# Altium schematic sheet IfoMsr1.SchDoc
size C; Engineer: Daniel Sigg; DocumentNumber: 4; SheetNumber: 4; SheetTotal: 33
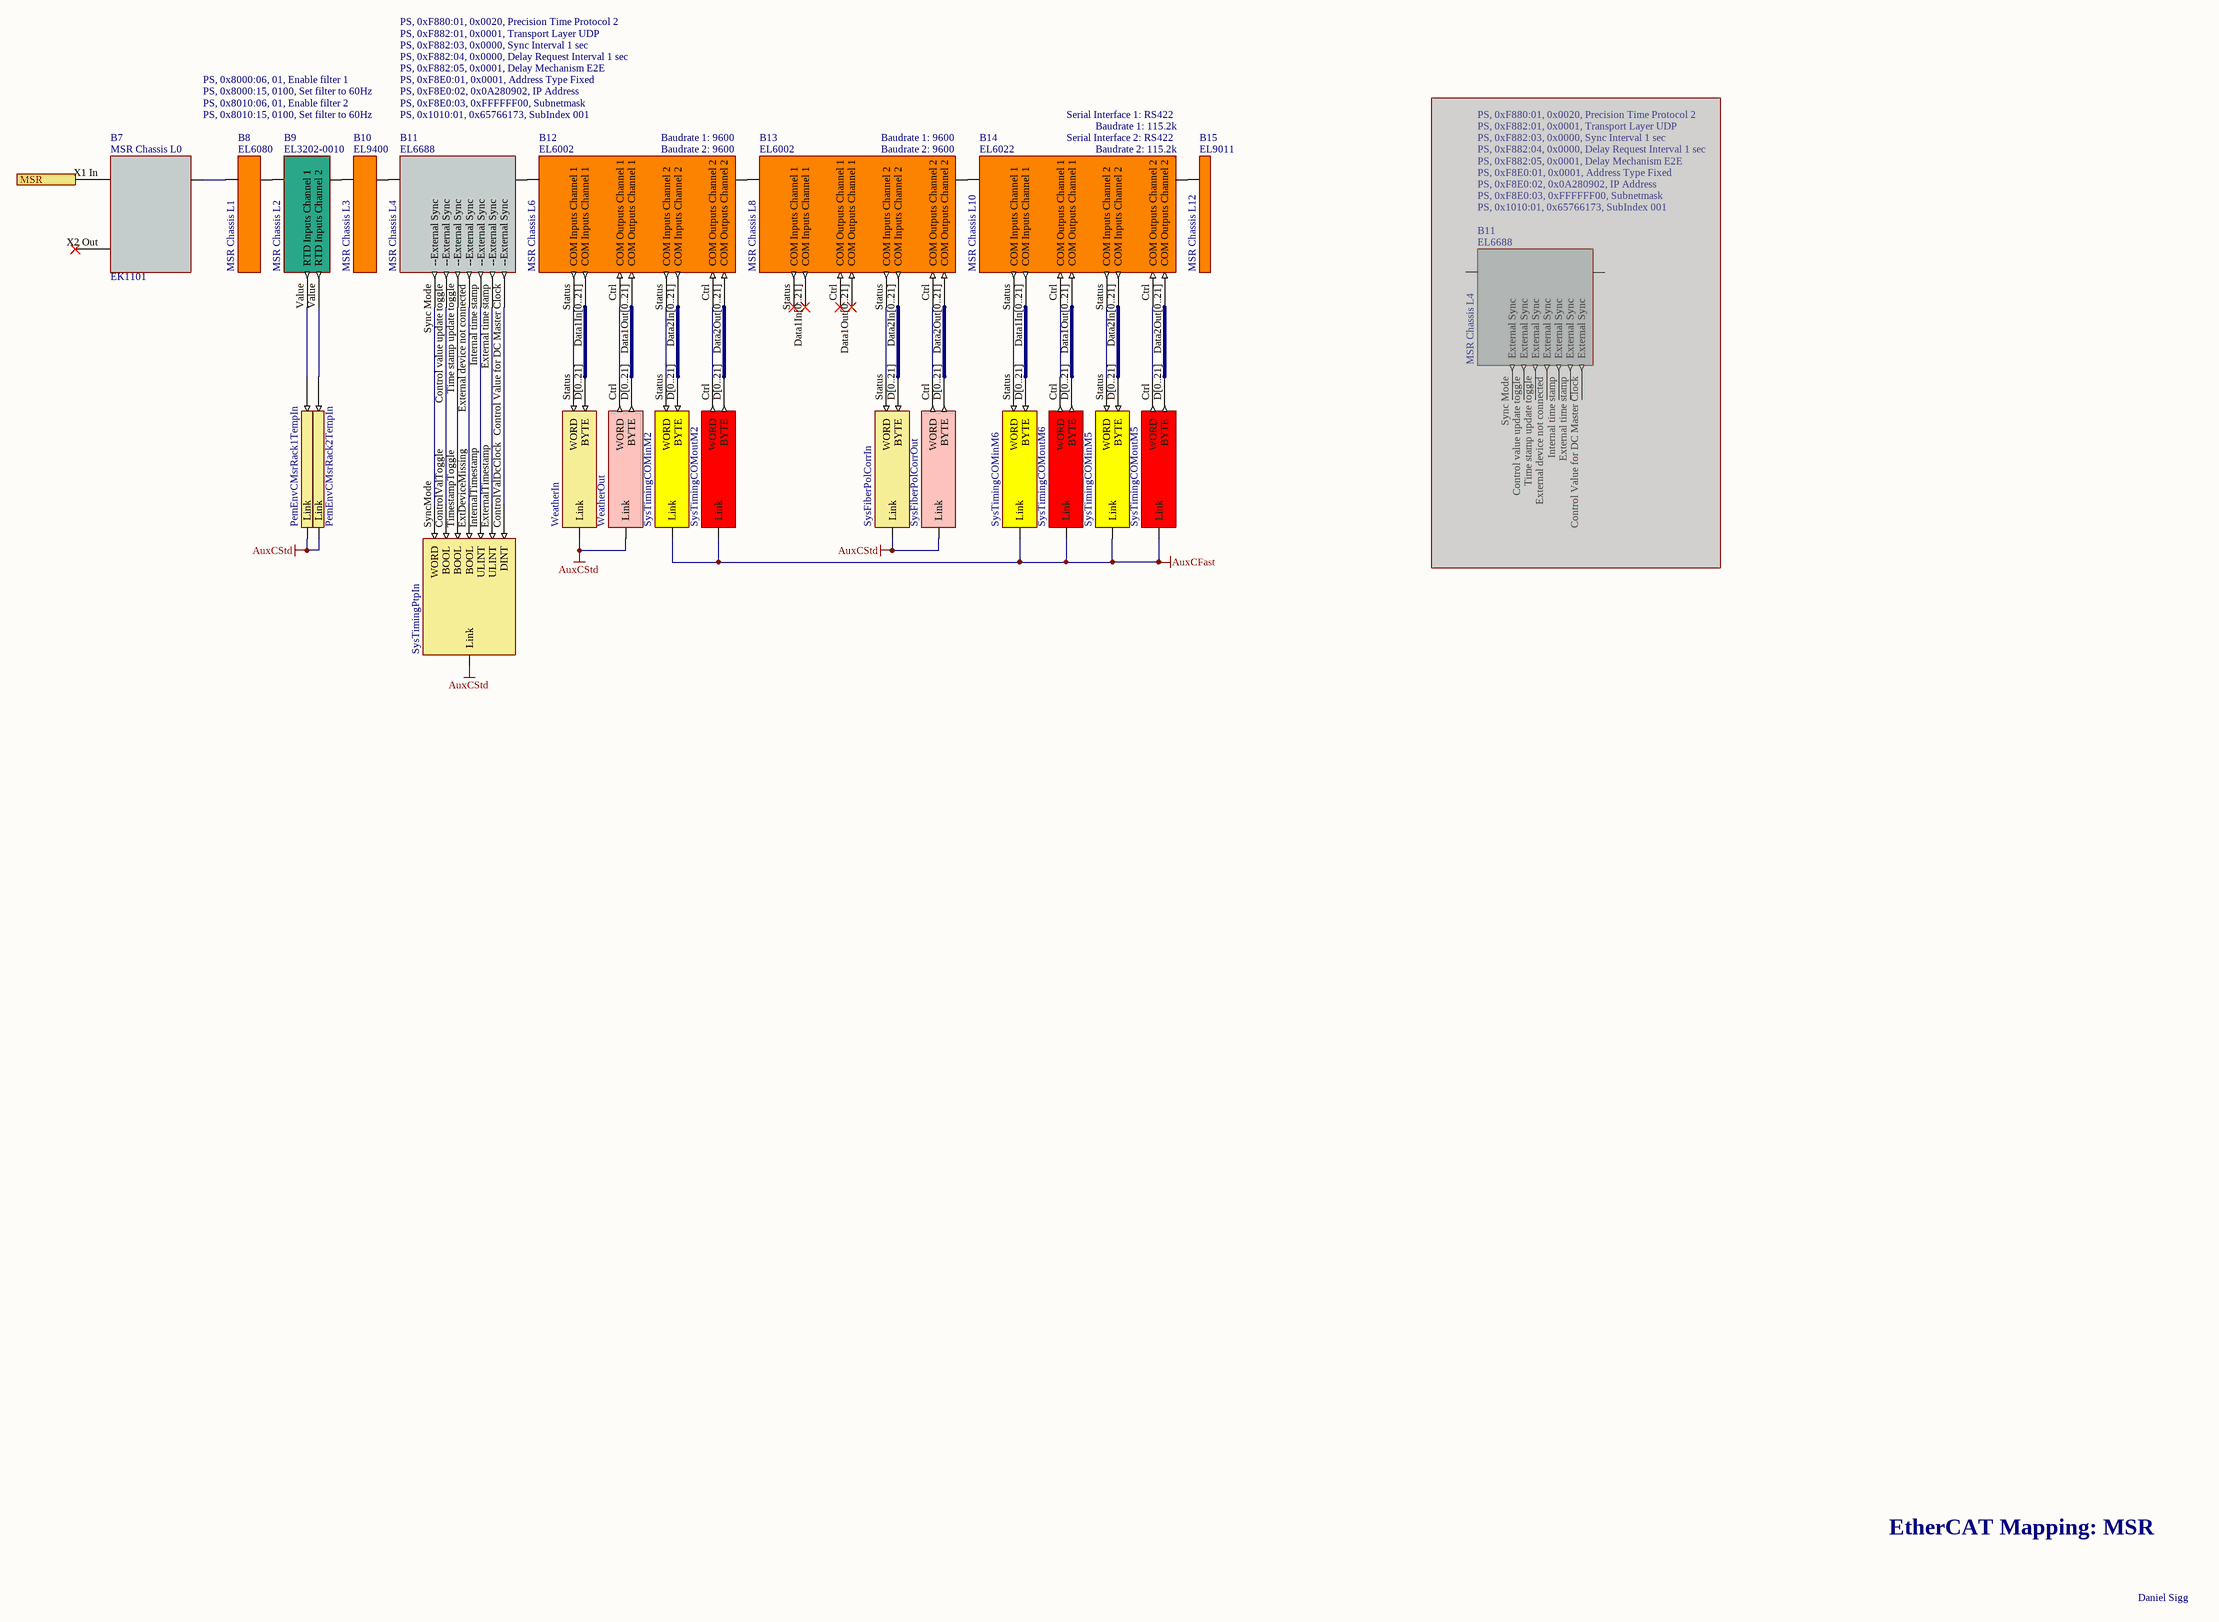
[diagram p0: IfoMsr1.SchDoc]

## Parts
(Parts that share a designator on the sheet are numbered #1, #2 ... from top to bottom, then left to right.)
B7  MSR Chassis L0  Part Number: EK1101  (mechanical)
B8  MSR Chassis L1  Part Number: EL6080  (mechanical)
B9  MSR Chassis L2  Part Number: EL3202-0010  Init0Cmd: PS, 0x8000:06, 01, Enable filter 1  Init1Cmd: PS, 0x8000:15, 0100, Set filter to 60Hz  Init2Cmd: PS, 0x8010:06, 01, Enable filter 2  Init3Cmd: PS, 0x8010:15, 0100, Set filter to 60Hz  (mechanical)
B10  MSR Chassis L3  Part Number: EL9400  (mechanical)
B11#1  MSR Chassis L4  Init3Cmd: PS, 0xF882:04, 0x0000, Delay Request Interval 1 sec  Init4Cmd: PS, 0xF882:05, 0x0001, Delay Mechanism E2E  Init5Cmd: PS, 0xF8E0:01, 0x0001, Address Type Fixed  Init6Cmd: PS, 0xF8E0:02, 0x0A280902, IP Address  Init7Cmd: PS, 0xF8E0:03, 0xFFFFFF00, Subnetmask  Init8Cmd: PS, 0x1010:01, 0x65766173, SubIndex 001  Init2Cmd: PS, 0xF882:03, 0x0000, Sync Interval 1 sec  Init1Cmd: PS, 0xF882:01, 0x0001, Transport Layer UDP  Init0Cmd: PS, 0xF880:01, 0x0020, Precision Time Protocol 2  Part Number: EL6688  (mechanical)
B11#2  MSR Chassis L4  Init3Cmd: PS, 0xF882:04, 0x0000, Delay Request Interval 1 sec  Init4Cmd: PS, 0xF882:05, 0x0001, Delay Mechanism E2E  Init5Cmd: PS, 0xF8E0:01, 0x0001, Address Type Fixed  Init6Cmd: PS, 0xF8E0:02, 0x0A280902, IP Address  Init7Cmd: PS, 0xF8E0:03, 0xFFFFFF00, Subnetmask  Init8Cmd: PS, 0x1010:01, 0x65766173, SubIndex 001  Init2Cmd: PS, 0xF882:03, 0x0000, Sync Interval 1 sec  Init1Cmd: PS, 0xF882:01, 0x0001, Transport Layer UDP  Init0Cmd: PS, 0xF880:01, 0x0020, Precision Time Protocol 2  Part Number: EL6688  (mechanical)  (masked out: inside a compile mask, not in the netlist)
B12  MSR Chassis L6  Part Number: EL6002  Baudrate 1: 9600  (mechanical)
B13  MSR Chassis L8  Part Number: EL6002  Baudrate 1: 9600  (mechanical)
B14  MSR Chassis L10  Part Number: EL6022  Baudrate 1: 115.2k  Serial Interface 1: RS422  (mechanical)
B15  MSR Chassis L12  Part Number: EL9011  (mechanical)
V95  PemEnvCMsrRack1TempIn  (no BOM)
V96  PemEnvCMsrRack2TempIn  (no BOM)
V99  SysTimingCOMinM2  (no BOM)
V100  SysTimingCOMoutM2  (no BOM)
V101  SysFiberPolCorrIn  (no BOM)
V102  SysFiberPolCorrOut  (no BOM)
V103  SysTimingCOMinM5  (no BOM)
V104  SysTimingCOMoutM5  (no BOM)
V827  SysTimingCOMinM6  (no BOM)
V828  SysTimingCOMoutM6  (no BOM)
V839  SysTimingPtpIn  (no BOM)
V843  WeatherIn  (no BOM)
V844  WeatherOut  (no BOM)

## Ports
MSR

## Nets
AuxCFast: V99.?1(Link) V100.?1(Link) V103.?1(Link) V104.?1(Link) V827.?1(Link) V828.?1(Link)
AuxCStd: V95.?2(Link) V96.?2(Link) V101.?1(Link) V102.?1(Link) V839.?1(Link) V843.?1(Link) V844.?1(Link)
MSR: B7.X1_In(A) ; port MSR
NetB7_Ebus: B7.Ebus(B) B8.Ebus(A)
NetB8_Ebus: B8.Ebus(B) B9.Ebus(A)
NetB9_Ebus: B9.Ebus(B) B10.Ebus(A)
NetB9_Value: B9.Value(RTD_Inputs_Channel_1) V95.?1
NetB9_Value: B9.Value(RTD_Inputs_Channel_2) V96.?1  [a separate net that carries the same name]
NetB10_Ebus: B10.Ebus(B) B11#1.Ebus(A)
NetB11#1_Control Value for DC Master Clock: B11#1.Control_Value_for_DC_Master_Clock(­­External_Sync) V839.ControlValDcClock(DINT)
NetB11#1_Control value update toggle: B11#1.Control_value_update_toggle(­­External_Sync) V839.ControlValToggle(BOOL)
NetB11#1_Ebus: B11#1.Ebus(B) B12.Ebus(A)
NetB11#1_External device not connected: B11#1.External_device_not_connected(­­External_Sync) V839.ExtDeviceMissing(BOOL)
NetB11#1_External time stamp: B11#1.External_time_stamp(­­External_Sync) V839.ExternalTimestamp(ULINT)
NetB11#1_Internal time stamp: B11#1.Internal_time_stamp(­­External_Sync) V839.InternalTimestamp(ULINT)
NetB11#1_Sync Mode: B11#1.Sync_Mode(­­External_Sync) V839.SyncMode(WORD)
NetB11#1_Time stamp update toggle: B11#1.Time_stamp_update_toggle(­­External_Sync) V839.TimestampToggle(BOOL)
NetB12_Ctrl: B12.Ctrl(COM_Outputs_Channel_1) V844.Ctrl(WORD)
NetB12_Ctrl: B12.Ctrl(COM_Outputs_Channel_2) V100.Ctrl(WORD)  [a separate net that carries the same name]
NetB12_Data1In[0..21]: B12.Data1In[0..21](COM_Inputs_Channel_1) V843.D[0..21](BYTE)
NetB12_Data1Out[0..21]: B12.Data1Out[0..21](COM_Outputs_Channel_1) V844.D[0..21](BYTE)
NetB12_Data2In[0..21]: B12.Data2In[0..21](COM_Inputs_Channel_2) V99.D[0..21](BYTE)
NetB12_Data2Out[0..21]: B12.Data2Out[0..21](COM_Outputs_Channel_2) V100.D[0..21](BYTE)
NetB12_Ebus: B12.Ebus(B) B13.Ebus(A)
NetB12_Status: B12.Status(COM_Inputs_Channel_1) V843.Status(WORD)
NetB12_Status: B12.Status(COM_Inputs_Channel_2) V99.Status(WORD)  [a separate net that carries the same name]
NetB13_Ctrl: B13.Ctrl(COM_Outputs_Channel_1) V102.Ctrl(WORD)
NetB13_Data2In[0..21]: B13.Data2In[0..21](COM_Inputs_Channel_2) V101.D[0..21](BYTE)
NetB13_Data2Out[0..21]: B13.Data2Out[0..21](COM_Outputs_Channel_2) V102.D[0..21](BYTE)
NetB13_Ebus: B13.Ebus(B) B14.Ebus(A)
NetB13_Status: B13.Status(COM_Inputs_Channel_1) V101.Status(WORD)
NetB14_Ctrl: B14.Ctrl(COM_Outputs_Channel_1) V828.Ctrl(WORD)
NetB14_Ctrl: B14.Ctrl(COM_Outputs_Channel_2) V104.Ctrl(WORD)  [a separate net that carries the same name]
NetB14_Data1In[0..21]: B14.Data1In[0..21](COM_Inputs_Channel_1) V827.D[0..21](BYTE)
NetB14_Data1Out[0..21]: B14.Data1Out[0..21](COM_Outputs_Channel_1) V828.D[0..21](BYTE)
NetB14_Data2In[0..21]: B14.Data2In[0..21](COM_Inputs_Channel_2) V103.D[0..21](BYTE)
NetB14_Data2Out[0..21]: B14.Data2Out[0..21](COM_Outputs_Channel_2) V104.D[0..21](BYTE)
NetB14_Ebus: B14.Ebus(B) B15.Ebus(A)
NetB14_Status: B14.Status(COM_Inputs_Channel_1) V827.Status(WORD)
NetB14_Status: B14.Status(COM_Inputs_Channel_2) V103.Status(WORD)  [a separate net that carries the same name]

Not connected (* = marked no-connect by the designer): B7 X2 Out(C)*; B13 Data1In[0..21](COM_Inputs_Channel_1)* Data1Out[0..21](COM_Outputs_Channel_1)*

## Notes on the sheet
- EtherCAT Mapping: MSR
- Daniel Sigg

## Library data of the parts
B7 = CouplerEK1101: EtherCAT Coupler; Rail: Left; BoxNextB: DTWVYLGW; BoxPrev: LHTDNYMI; PortPrevFull: 1000/; Fullname: TIID^Vertex MSR (EtherCAT)^MSR Chassis L0 (EK1101); BoxPorts: Junction; BoxAddr: 1001; Disabled: False
B8 = TerminalEL6080: EtherCAT Terminal EL6080 Memory; Rail: Left; BoxNextB: QXEOUGJE; BoxPrev: DRMHDDTT; PortPrevFull: 1001/B; PortPrevShort: B; Fullname: TIID^Vertex MSR (EtherCAT)^MSR Chassis L0 (EK1101)^MSR Chassis L1 (EL6080); BoxAddr: 1002; Disabled: False
B9 = TerminalEL3202-0010: EtherCAT Terminal EL3202-0010 2-chn Temperature Input; Rail: Left; BoxNextB: QBNRREKQ; BoxPrev: DTWVYLGW; PortPrevFull: 1002/B; PortPrevShort: B; Fullname: TIID^Vertex MSR (EtherCAT)^MSR Chassis L0 (EK1101)^MSR Chassis L2 (EL3202-0010); BoxAddr: 1003; Disabled: False
B10 = TerminalEL9400: EtherCAT Terminal EL9400 Power; BoxType: TerminalPassive; Rail: Left; BoxNextB: UXPGGLQP; BoxPrev: QXEOUGJE; PortPrevShort: B; Fullname: TIID^Vertex MSR (EtherCAT)^MSR Chassis L0 (EK1101)^MSR Chassis L3 (EL9400); Disabled: False
B11#1 = TerminalEL6688: EtherCAT Terminal EL6688 Clock; Disabled: False
B11#2 = TerminalEL6688: EtherCAT Terminal EL6688 Clock; Rail: Left; BoxNextB: CYQBPVIK; BoxPrev: QBNRREKQ; PortPrevFull: 1003/B; PortPrevShort: B; Fullname: TIID^Vertex MSR (EtherCAT)^MSR Chassis L0 (EK1101)^MSR Chassis L4 (EL6688); BoxAddr: 1004; Disabled: False
B12 = TerminalEL6002: EtherCAT Terminal EL6002 Dual RS232; Rail: Left; BoxNextB: RTMBOGVS; BoxPrev: UXPGGLQP; PortPrevFull: 1004/B; PortPrevShort: B; Fullname: TIID^Vertex MSR (EtherCAT)^MSR Chassis L0 (EK1101)^MSR Chassis L6 (EL6002); BoxAddr: 1005; BoxSubType: 9101; Disabled: False
B13 = TerminalEL6002: EtherCAT Terminal EL6002 Dual RS232; Rail: Left; BoxNextB: DQXTOCMA; BoxPrev: CYQBPVIK; PortPrevFull: 1005/B; PortPrevShort: B; Fullname: TIID^Vertex MSR (EtherCAT)^MSR Chassis L0 (EK1101)^MSR Chassis L8 (EL6002); BoxAddr: 1006; BoxSubType: 9101; Disabled: False
B14 = TerminalEL6022: EtherCAT Terminal EL6022 Dual RS422; Rail: Left; BoxNextB: UIOOYRBM; BoxPrev: RTMBOGVS; PortPrevFull: 1006/B; PortPrevShort: B; Fullname: TIID^Vertex MSR (EtherCAT)^MSR Chassis L0 (EK1101)^MSR Chassis L10 (EL6022); BoxAddr: 1007; BoxSubType: 9103; Disabled: False
B15 = TerminalEL9011: EtherCAT Terminal EL9011 End; BoxType: TerminalPassive; Rail: Left; BoxPrev: DQXTOCMA; PortPrevShort: B; Fullname: TIID^Vertex MSR (EtherCAT)^MSR Chassis L0 (EK1101)^MSR Chassis L12 (EL9011); Disabled: False
V95 V96 = VariableInINT: INT; PLC: H1AuxCorner; Task: AuxCStd; Instance: H1AuxCorner Instance
V99 V103 V827 = Serial_EL6inData22Bfast: EL6inData22B; PLC: H1AuxCorner; Task: AuxCFast; BoxType: Variable; Instance: H1AuxCorner Instance
V100 V104 V828 = Serial_EL6outData22Bfast: EL6outData22B; PLC: H1AuxCorner; Task: AuxCFast; BoxType: Variable; Instance: H1AuxCorner Instance
V101 V843 = Serial_EL6inData22B: EL6inData22B; PLC: H1AuxCorner; Task: AuxCStd; BoxType: Variable; Instance: H1AuxCorner Instance
V102 V844 = Serial_EL6outData22B: EL6outData22B; PLC: H1AuxCorner; Task: AuxCStd; BoxType: Variable; Instance: H1AuxCorner Instance
V839 = Ptp_PtpInStruct: PtpInStruct; BoxType: Variable; Instance: H1AuxCorner Instance; PLC: H1AuxCorner; Task: AuxCStd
